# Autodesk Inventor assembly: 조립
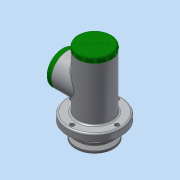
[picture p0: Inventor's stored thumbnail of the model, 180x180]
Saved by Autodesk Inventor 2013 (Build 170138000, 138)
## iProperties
Created: 2016-08
Part Number: 조립
Document SubType Name: Assembly
Designer: dgall
Author: dgall
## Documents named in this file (25)
- C:\Users\dgall\Desktop\460807V1010\조립.iam
- C:\Users\dgall\Desktop\460807V1010\본체.ipt
- C:\Users\dgall\Desktop\460807V1010\너트 M10.ipt
- C:\Users\dgall\Desktop\460807V1010\링크.ipt
- C:\Users\dgall\Desktop\460807V1010\멈춤링 15 x 1.ipt
- C:\Users\dgall\Desktop\460807V1010\멈춤링 35x1.6.ipt
- C:\Users\dgall\Desktop\460807V1010\베어링 15 x 35 x 11.ipt
- C:\Users\dgall\Desktop\460807V1010\V-벨트풀리.ipt
- C:\Users\dgall\Desktop\460807V1010\볼트 M4 x 10.ipt
- C:\Users\dgall\Desktop\460807V1010\볼트 M4 x 12.ipt
- C:\Users\dgall\Desktop\460807V1010\부시1.ipt
- C:\Users\dgall\Desktop\460807V1010\부시2.ipt
- C:\Users\dgall\Desktop\460807V1010\분할핀 1.6 x 12.ipt
- C:\Users\dgall\Desktop\460807V1010\사이드 커버.ipt
- 사이드 커버.ipt
- C:\Users\dgall\Desktop\460807V1010\슬라이더.ipt
- C:\Users\dgall\Desktop\460807V1010\오일 실 15 25 7.ipt
- C:\Users\dgall\Desktop\460807V1010\와셔 4x16.ipt
- C:\Users\dgall\Desktop\460807V1010\와셔 10x21.ipt
- C:\Users\dgall\Desktop\460807V1010\클래스터 핀 6 x 24.ipt
- C:\Users\dgall\Desktop\460807V1010\키 4 x 4 x 18.ipt
- C:\Users\dgall\Desktop\460807V1010\탑 부시.ipt
- C:\Users\dgall\Desktop\460807V1010\탑 커버.ipt
- 탑 커버.ipt
- C:\Users\dgall\Desktop\460807V1010\편심축.ipt
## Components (6 placed, 3 different names)
1. V-벨트풀리:1
2. ISO 4017 M4 x 10:1
3. ISO 4762 M4 x 12:1
4. ISO 4762 M4 x 12:2
5. ISO 4762 M4 x 12:3
6. ISO 4762 M4 x 12:4
